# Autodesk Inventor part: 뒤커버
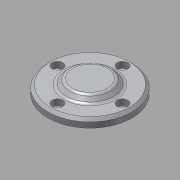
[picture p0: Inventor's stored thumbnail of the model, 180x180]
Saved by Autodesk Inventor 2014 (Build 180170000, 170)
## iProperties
Created: 2015-09
Part Number: 뒤커버
Material: 알루미늄 6061
Document SubType Name: Modeling
Designer: mduedu
Density: 1 g/cm^3
Appearance: Aluminum - Flat
Author: mduedu
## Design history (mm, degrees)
sketch "스케치1"
  geometry: L1 (0, 7.5)-(0, -7.5); L2 (0, 7.5)-(14, 7.5); L3 (14, 7.5)-(18, 3.5); L4 (18, 3.5)-(31, 3.5); L5 (31, 3.5)-(31, -2.5); L6 (31, -2.5)-(17.5, -2.5); L7 (17.5, -2.5)-(17.5, -7.5); L8 (17.5, -7.5)-(0, -7.5); 2 further points
  constraints: 16 end point, 3 parallel, 2 perpendicular, 1 coincident, 1 horizontal, 1 midpoint, 1 vertical
  dimensions: "d0" = 15 distance of L1.start L1.end; "d1" = 4 distance between parallel lines of L4 L2; "d2" = 6 distance of L4.end L5.end; "d3" = 36 diameter of L3.end L1; "d4" = 35 diameter of L7 L1; "d5" = 62 diameter of L5 L1; "d7" = 45 deg angle of L3 L5
revolve "회전1" sketch "스케치1" stored, may be unused: angle "d8" = 90 deg
hole "구멍1" diameter "d11" = 24; stored, may be unused: countersink angle "d15" = 90 deg, drill point angle "d17" = 0 deg; dims "d9" = 10, "d10" = 10, "d12" = 6, "d13" = 4, "d14" = 2, "d16" = 8
fillet "모깎기1" dims "d18" = 3
chamfer "모따기1" distance "d19" = 1; stored, may be unused: second distance "d20" = 2, angle "d21" = 45 deg
chamfer "모따기2" distance "d22" = 2; stored, may be unused: second distance "d23" = 2, angle "d24" = 45 deg
fillet "모깎기2" dims "d25" = 3
fillet "모깎기3" dims "d26" = 3
sketch "스케치2" dims "d27" = 48
  geometry: 6 further points
  constraints: 2 vertical alignment, 1 coincident, 7 other
  dimensions: "d33" = 360 deg dimension on point (0, 0) point (0, 24) (derived)
sketch "스케치3"
  geometry: 4 further points
hole "구멍2" sketch "스케치3" at (-24, 0), (0, -24), (24, 0), (0, 24) diameter "d35" = 4.5; stored, may be unused: countersink angle "d39" = 90 deg, drill point angle "d41" = 0 deg; dims "d36" = 6, "d37" = 8, "d38" = 4.6, "d40" = 8
node "솔리드1"
